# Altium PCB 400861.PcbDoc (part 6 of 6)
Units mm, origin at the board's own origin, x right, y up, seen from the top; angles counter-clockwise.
Board outline 145 x 63.5 mm, 8 copper layers (Top Side, Mid-Layer 1, Mid-Layer 2, Mid-Layer 3, Mid-Layer 4, Mid-Layer 5, Mid-Layer 6, Bottom Side), stack 1.529 mm thick; 284 components, 233 nets, 1158 pads, 3522 vias.
Unrouted connection lines stored in the file: 1.
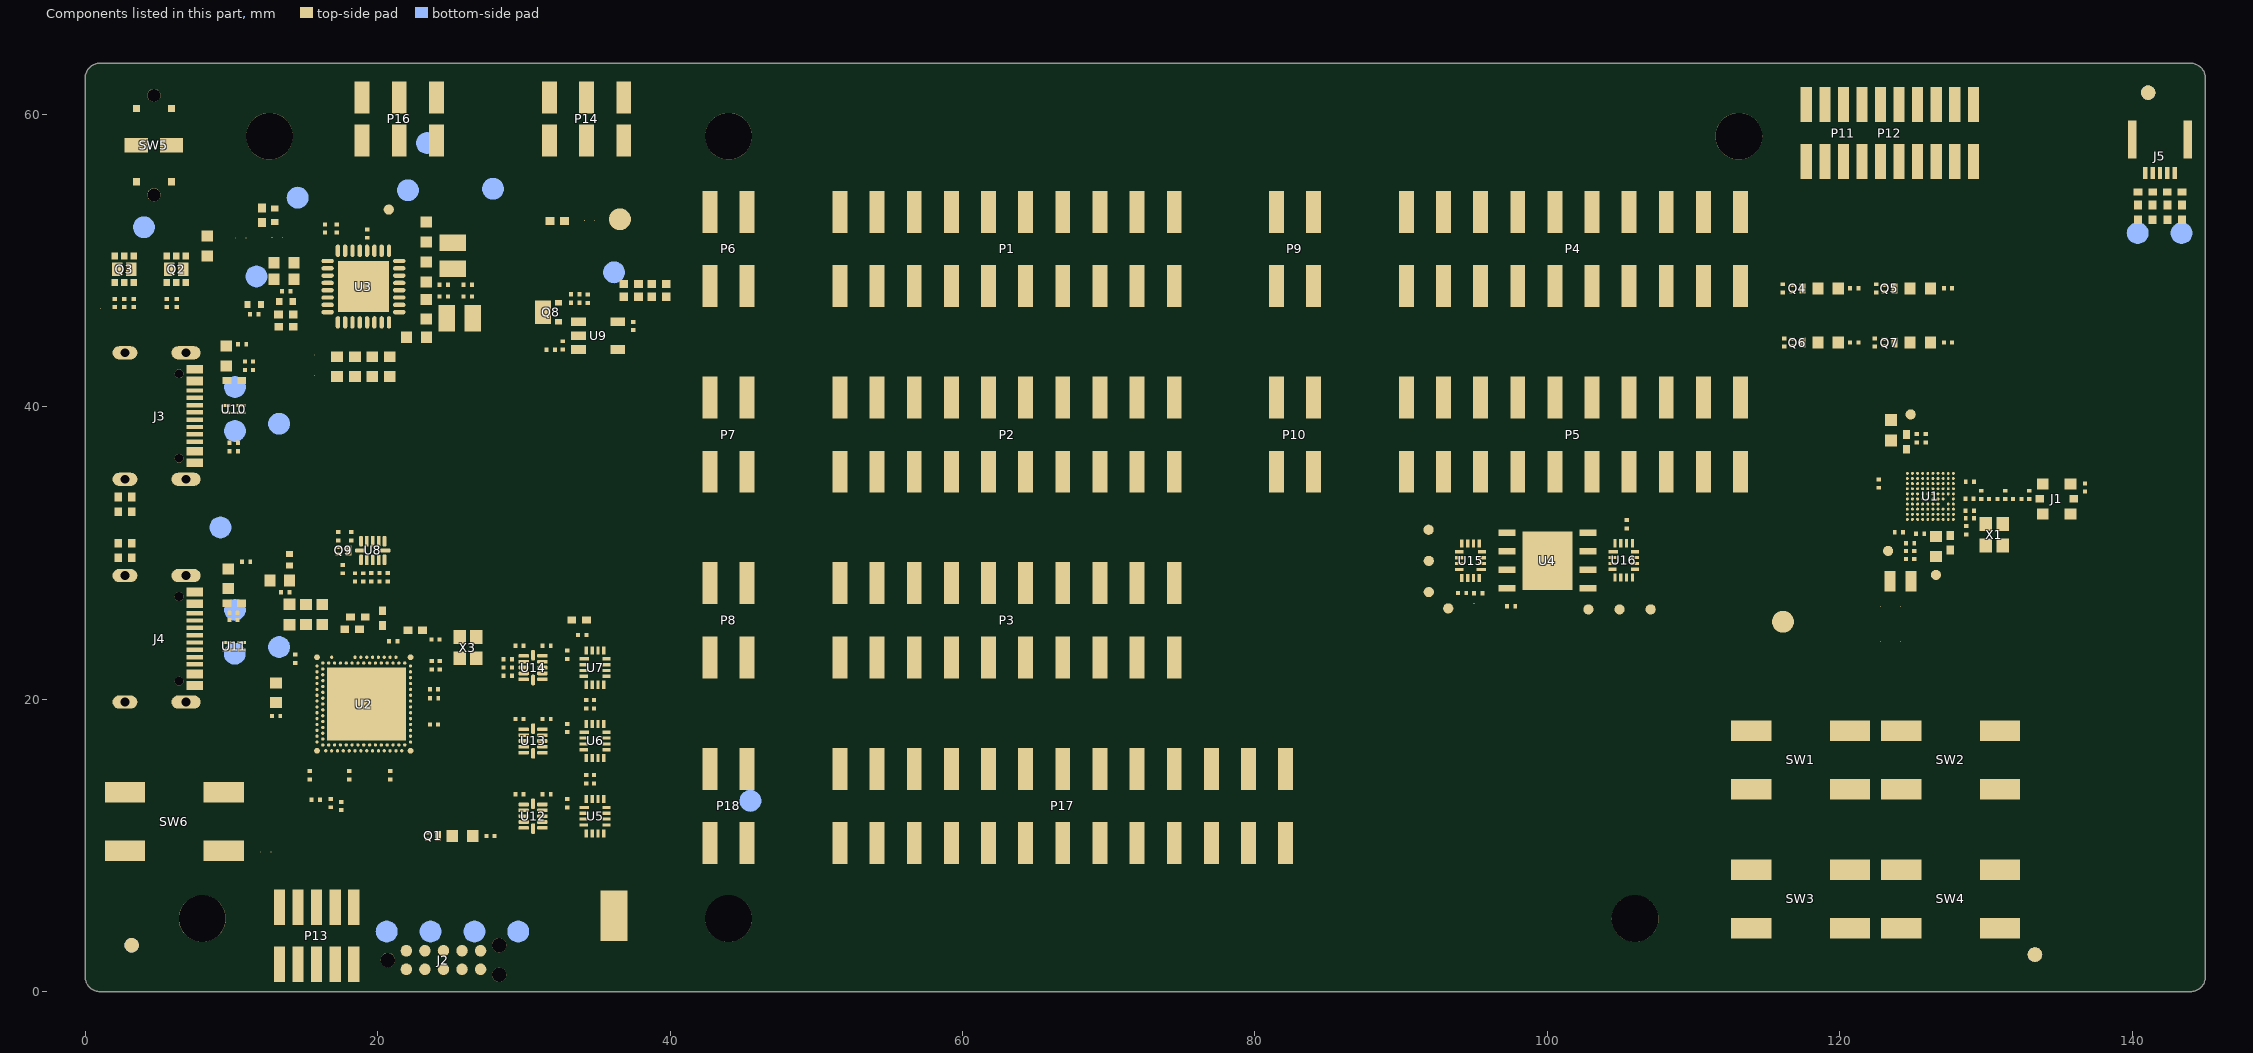
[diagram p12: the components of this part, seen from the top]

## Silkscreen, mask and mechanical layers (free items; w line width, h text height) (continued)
Bottom Overlay:
  drawing of 205 lines, arcs and shapes, not listed
  text "(P5V0)" at 18.86,58.517 h0.64 r180
  text "(P5V0_LED)" at 25.991,53.645 h0.64 r180
  text "(P3V3_IO)" at 19.461,53.545 h0.64 r180
  text "(VBUS)" at 2.36,51.05 h0.64 r180
  text "(GND)" at 10.405,47.385 h0.64 r180
  text "P1.19" at 62.004,47.186 h1.91 r180
  text "CTS1" at 68.87,47.076 h1.91 r180
  text "(GND)" at 37.65,46.95 h0.64
  text "NRESET" at 87.806,46.67 h1.91 r180
  text "nRF54" at 101.949,46.134 h2.03 r180
  text "P1.18" at 62,44.386 h1.91 r180
  text "RTS1" at 68.87,44.383 h1.91 r180
  text "nRF54" at 76.888,44.34 h2.03 r180
  text "SWDCLK" at 87.806,43.041 h1.91 r180
  text "P1.17" at 62,41.686 h1.91 r180
  text "RXD1" at 68.87,41.667 h1.91 r180
  text "(nRF54_P)" at 3.666,41.617 h0.64 r180
  text "DEBUGGER" at 102.025,40.037 h1.4 r180
  text "SWDIO" at 87.806,39.413 h1.91 r180
  text "P1.16" at 62,38.986 h1.91 r180
  text "TXD1" at 68.87,38.962 h1.91 r180
  text "(nRF54_N)" at 3.666,38.617 h0.64 r180
  text "PIN" at 76.517,38.54 h1.78 r180
  text "P0.09" at 62,36.286 h1.91 r180
  text "CTS0" at 68.87,36.302 h1.91 r180
  text "P0.05" at 87.8,36.286 h1.91 r180
  text "Button 3" at 93.724,36.29 h1.91 r180
  text "RTS0" at 68.87,33.61 h1.91 r180
  text "P1.08" at 87.8,33.586 h1.91 r180
  text "Button 2" at 93.724,33.598 h1.91 r180
  text "P0.08" at 62.001,33.561 h1.91 r180
  text "RXD0" at 68.87,30.904 h1.91 r180
  text "Button 1" at 93.724,30.905 h1.91 r180
  text "P0.07" at 61.993,30.816 h1.91 r180
  text "P1.09" at 87.792,30.816 h1.91 r180
  text "(GND)" at 7.95,30.55 h0.64 r180
  text "DEBUGGER" at 76.536,30.211 h1.4 r180
  text "Button 0" at 93.724,28.904 h1.91 r180
  text "P0.06" at 62.001,28.286 h1.91 r180
  text "TXD0" at 68.87,28.212 h1.91 r180
  text "P1.26" at 87.806,28.213 h1.91 r180
  text "(DBGR_N)" at 4.301,26.38 h0.64 r180
  text "P1.28" at 87.806,25.521 h1.91 r180
  text "LED 3" at 93.724,25.508 h1.91 r180
  text "GPIO" at 75.5,25.025 h1.78 r180
  text "P1.02" at 62,24.086 h1.91 r180
  text "NFC2" at 68.87,24.046 h1.91 r180
  text "1M" at 102.675,23.838 h1.27 r180
  text "(DBGR_P)" at 4.301,23.38 h0.64 r180
  text "P1.27" at 87.806,22.828 h1.91 r180
  text "LED 2" at 93.724,22.828 h1.91 r180
  text "0R" at 79.348,22.584 h1.27 r180
  text "N.C" at 76.031,21.88 h1.27 r180
  text "NFC" at 80.351,20.979 h1.78 r180
  text "P1.25" at 87.806,20.136 h1.91 r180
  text "LED 1" at 93.724,20.112 h1.91 r180
  text "P1.01" at 62,18.886 h1.91 r180
  text "NFC1" at 68.972,18.891 h1.91 r180
  text "PIN" at 77.405,17.851 h1.78 r180
  text "P1.22" at 87.806,17.443 h1.91 r180
  text "LED 0" at 93.724,17.441 h1.91 r180
  text "5.0V" at 106.262,16.915 h1.27 r180
  text "GPIO" at 61.123,15.539 h1.78 r180
  text "FUNCTION" at 66.553,15.539 h1.78 r180
  text "HW" at 75.246,15.539 h1.78 r180
  text "GPIO" at 86.967,15.539 h1.78 r180
  text "FUNCTION" at 92.683,15.539 h1.78 r180
  text "HW" at 100.934,15.539 h1.78 r180
  text "(GND)" at 44.205,11.485 h0.64 r180
  text "(VDD_DBGR)" at 20.703,6.373 h0.64 r270
  text "(DBGR_RESET)" at 23.624,6.373 h0.64 r270
  text "(DBGR_SWDIO)" at 26.592,6.373 h0.64 r270
  text "(DBGR_SWDCLK)" at 29.593,6.373 h0.64 r270
Board Outline:
  lines w0.2: 1,0 cw(c1,1) 0,1 0,62.5 cw(c1,62.5) 1,63.5 144.002,63.5 ; 1.001,0 144,0 ccw(c144,1) 145,1 145,62.5 ccw(c144,62.5) 144,63.5
Top Impedance:
  lines w0.099: 7.485,38.62 ccw(c7.505,38.62) 7.505,38.6 8.4,38.6 ccw(c8.4,38.8) 8.6,38.8 8.6,39.6 ; 7.485,39.12 6.4,39.12 ; 7.555,39.55 cw(c7.555,39.62) 7.485,39.62 9.623,39.62 cw(c9.623,39.594) 9.65,39.594 ; 9.623,40.12 cw(c9.623,40.094) 9.65,40.094 7.427,40.094 cw(c7.427,40.12) 7.4,40.12 6.62,40.12 ccw(c6.62,39.9) 6.4,39.9 6.4,39.429 6.4,39.3 6.4,39.12 ; 6.4,39.12 6.4,39.12
  lines w0.1: 10.643,39.639 10.644,39.64 35.089,39.64 ccw(c35.089,41.609) 36.482,40.217 37.922,41.656 cw(c39.718,39.86) 39.718,42.4 127.717,42.4 cw(c127.717,41.718) 128.2,42.2 130.517,39.883 cw(c129.834,39.2) 130.8,39.2 130.8,35.9 ; 10.645,40.041 10.646,40.04 35.088,40.04 ccw(c35.088,41.613) 36.2,40.5 37.641,41.941 cw(c39.715,39.868) 39.715,42.8 127.72,42.8 cw(c127.72,41.725) 128.481,42.485 130.801,40.165 cw(c129.837,39.202) 131.2,39.202 131.2,35.9
  lines w0.102: 132.233,33.562 134.089,33.562 ; 134.659,33.562 135.159,33.562 135.689,33.562 ; 136.259,33.562 136.759,33.562 137.259,33.562 ; 137.829,33.562 138.599,33.562
  lines w0.125: 7.973,23.384 cw(c8.083,23.384) 8.083,23.494 9.589,23.494 cw(c9.589,23.383) 9.7,23.383 ; 7.973,23.884 ccw(c8.085,23.884) 8.085,23.772 9.589,23.772 ccw(c9.589,23.883) 9.7,23.883 ; 10.7,23.383 10.7,23.411 cw(c10.8,23.411) 10.8,23.511 12.229,23.511 cw(c12.229,23.375) 12.365,23.375 ; 10.7,23.883 ccw(c10.793,23.883) 10.793,23.789 12.229,23.789 ccw(c12.229,23.925) 12.365,23.925 ; 12.935,23.375 cw(c13.077,23.375) 13.077,23.517 15.692,23.517 cw(c15.692,22.96) 16.249,22.96 16.249,22.477 16.25,22.475 ; 12.935,23.925 ccw(c13.065,23.925) 13.065,23.795 15.692,23.795 cw(c15.692,22.96) 16.527,22.96 16.527,22.599 ccw(c16.65,22.599) 16.65,22.475
  lines w0.15: 8.434,38.828 11.591,31.864 ; 8.828,24.459 11.591,31.864 ; 11.475,24.482 11.591,31.864 ; 11.637,31.795 14.469,24.35 ; 51.061,41.33 55.536,33.705 ; 133.22,33.286 133.519,29.366 ; 133.545,29.366 135.069,33.427 ; 136.609,33.427 133.584,29.405 137.964,33.412
  text "(Mid-Layer 3)" at 66.74,32.272 h0.64
  text "90ohm Coplanar Differential" at 49.865,32.247 h0.64
  text "(Top-Layer)" at 30.65,31.587 h0.64
  text "90ohm Coplanar Differential" at 13.775,31.562 h0.64
  text "Reference layer: Mid-Layer 2 and 4" at 49.865,31.022 h0.64
  text "Reference layer: Mid-Layer 1" at 13.775,30.337 h0.64
  text "(Top-Layer)" at 128.573,28.282 h0.64
  text "50ohm Coplanar" at 118.268,28.123 h0.64
  text "Reference layer: Mid-Layer 1" at 118.268,26.898 h0.64

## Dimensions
0,0 to 12.6,58.5 on Dimension
0,0 to 8,5 on Dimension
0,0 to 106,5 on Dimension
0,0 to 44,5 on Dimension
0,0 to 8,5 on Dimension
0,0 to 1,63.5 on Dimension
0,0 to 145,1 on Dimension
